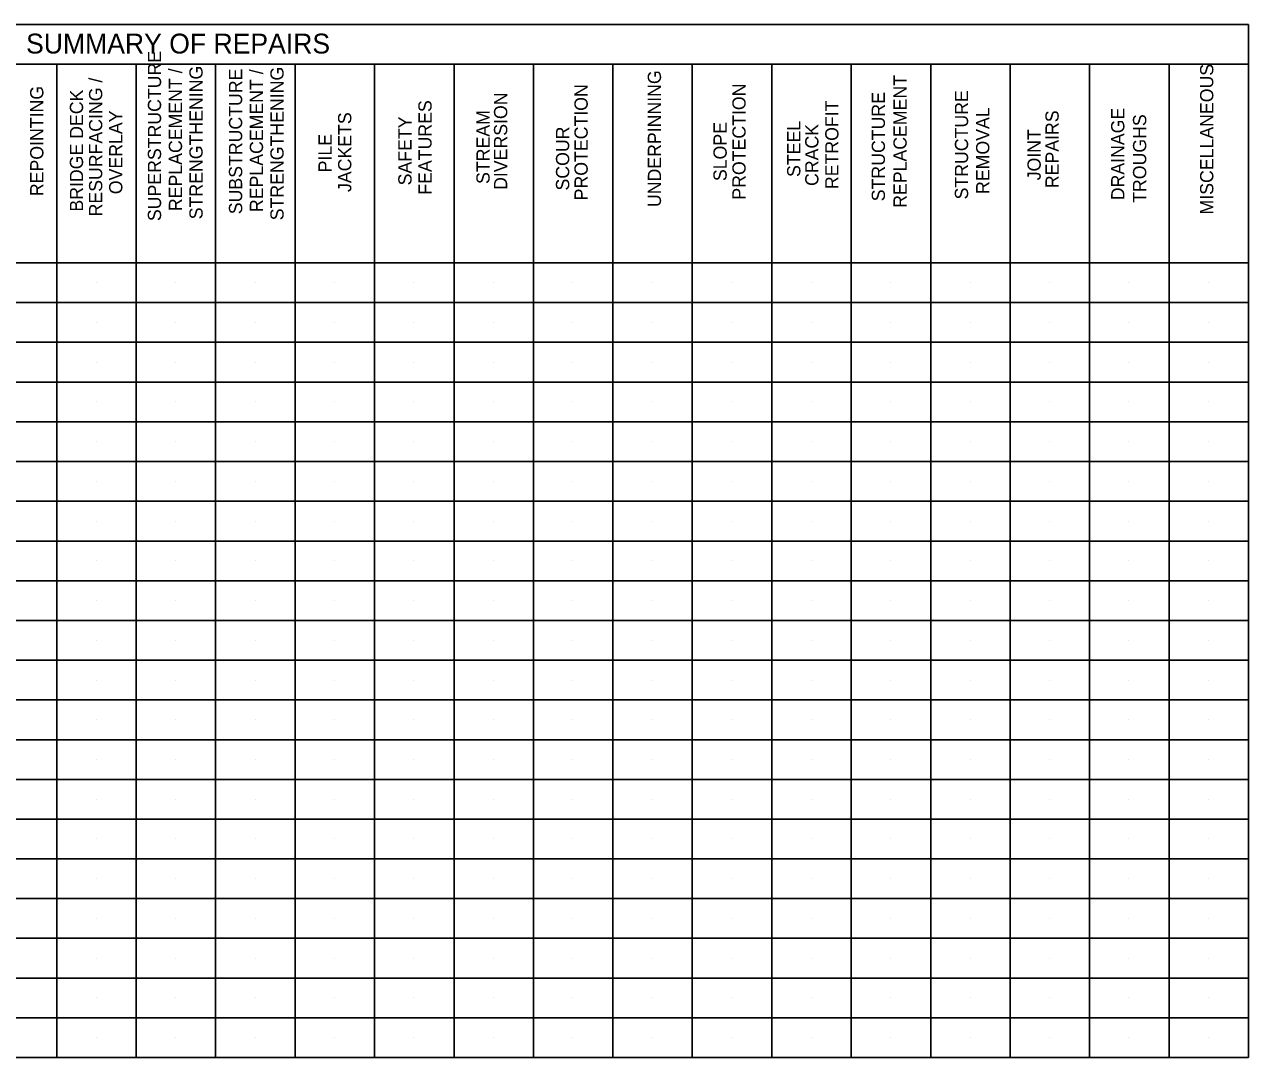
# Model space of a CAD drawing. Extents: x 3.4 to 29.9, y 7.8 to 20.1.
# Drawn here: x 15.32 to 29.88, y 7.79 to 20.08 of the extents above; entities that cross this region are included whole.
import ezdxf

# ---------------------------------------------------------------- set-up
doc = ezdxf.new("R2010")
doc.units = 0
doc.layers.add('ANNO-NOTE', color=7, linetype='Continuous')

msp = doc.modelspace()

# ---------------------------------------------------------------- linework, layer by layer
at = {"layer": 'ANNO-NOTE'}
for p, q in [((3.421, 20.077), (29.877, 20.077)), ((29.877, 20.077), (29.877, 7.794)), ((3.421, 19.605), (29.877, 19.605)), ((15.704, 17.242), (15.704, 19.605)), ((16.649, 17.242), (16.649, 19.605)), ((17.594, 17.242), (17.594, 19.605)), ((18.539, 17.242), (18.539, 19.605)), ((19.484, 17.242), (19.484, 19.605)), ((20.429, 17.242), (20.429, 19.605)), ((21.373, 17.242), (21.373, 19.605)), ((22.318, 17.242), (22.318, 19.605)), ((23.263, 17.242), (23.263, 19.605)), ((24.208, 17.242), (24.208, 19.605)), ((25.153, 17.242), (25.153, 19.605)), ((26.098, 17.242), (26.098, 19.605)), ((27.043, 17.242), (27.043, 19.605)), ((27.988, 17.242), (27.988, 19.605)), ((28.933, 17.242), (28.933, 19.605)), ((3.421, 17.242), (29.877, 17.242)), ((15.704, 17.242), (15.704, 7.794)), ((16.649, 17.242), (16.649, 7.794)), ((17.594, 17.242), (17.594, 7.794)), ((18.539, 17.242), (18.539, 7.794)), ((19.484, 17.242), (19.484, 7.794)), ((20.429, 17.242), (20.429, 7.794)), ((21.373, 17.242), (21.373, 7.794)), ((22.318, 17.242), (22.318, 7.794)), ((23.263, 17.242), (23.263, 7.794)), ((24.208, 17.242), (24.208, 7.794)), ((25.153, 17.242), (25.153, 7.794)), ((26.098, 17.242), (26.098, 7.794)), ((27.043, 17.242), (27.043, 7.794)), ((27.988, 17.242), (27.988, 7.794)), ((28.933, 17.242), (28.933, 7.794)), ((16.173, 17.006), (16.173, 17.006)), ((16.173, 17.006), (16.173, 17.006)), ((17.118, 17.006), (17.118, 17.006)), ((17.118, 17.006), (17.118, 17.006)), ((18.063, 17.006), (18.063, 17.006)), ((18.063, 17.006), (18.063, 17.006)), ((19.007, 17.006), (19.007, 17.006)), ((19.007, 17.006), (19.007, 17.006)), ((19.952, 17.006), (19.952, 17.006)), ((19.952, 17.006), (19.952, 17.006)), ((20.897, 17.006), (20.897, 17.006)), ((20.897, 17.006), (20.897, 17.006)), ((21.842, 17.006), (21.842, 17.006)), ((21.842, 17.006), (21.842, 17.006)), ((22.787, 17.006), (22.787, 17.006)), ((22.787, 17.006), (22.787, 17.006)), ((23.732, 17.006), (23.732, 17.006)), ((23.732, 17.006), (23.732, 17.006)), ((24.677, 17.006), (24.677, 17.006)), ((24.677, 17.006), (24.677, 17.006)), ((25.622, 17.006), (25.622, 17.006)), ((25.622, 17.006), (25.622, 17.006)), ((26.567, 17.006), (26.567, 17.006)), ((26.567, 17.006), (26.567, 17.006)), ((27.511, 17.006), (27.511, 17.006)), ((27.511, 17.006), (27.511, 17.006)), ((28.456, 17.006), (28.456, 17.006)), ((28.456, 17.006), (28.456, 17.006)), ((29.401, 17.006), (29.401, 17.006)), ((29.401, 17.006), (29.401, 17.006)), ((3.421, 16.77), (29.877, 16.77)), ((16.173, 16.534), (16.173, 16.534)), ((16.173, 16.534), (16.173, 16.534)), ((16.173, 16.534), (16.173, 16.534)), ((17.118, 16.534), (17.118, 16.534)), ((17.118, 16.534), (17.118, 16.534)), ((17.118, 16.534), (17.118, 16.534)), ((18.063, 16.534), (18.063, 16.534)), ((18.063, 16.534), (18.063, 16.534)), ((18.063, 16.534), (18.063, 16.534)), ((19.007, 16.534), (19.007, 16.534)), ((19.007, 16.534), (19.007, 16.534)), ((19.007, 16.534), (19.007, 16.534)), ((19.952, 16.534), (19.952, 16.534)), ((19.952, 16.534), (19.952, 16.534)), ((19.952, 16.534), (19.952, 16.534)), ((20.897, 16.534), (20.897, 16.534)), ((20.897, 16.534), (20.897, 16.534)), ((20.897, 16.534), (20.897, 16.534)), ((21.842, 16.534), (21.842, 16.534)), ((21.842, 16.534), (21.842, 16.534)), ((21.842, 16.534), (21.842, 16.534)), ((22.787, 16.534), (22.787, 16.534)), ((22.787, 16.534), (22.787, 16.534)), ((22.787, 16.534), (22.787, 16.534)), ((23.732, 16.534), (23.732, 16.534)), ((23.732, 16.534), (23.732, 16.534)), ((23.732, 16.534), (23.732, 16.534)), ((24.677, 16.534), (24.677, 16.534)), ((24.677, 16.534), (24.677, 16.534)), ((24.677, 16.534), (24.677, 16.534)), ((25.622, 16.534), (25.622, 16.534)), ((25.622, 16.534), (25.622, 16.534)), ((25.622, 16.534), (25.622, 16.534)), ((26.567, 16.534), (26.567, 16.534)), ((26.567, 16.534), (26.567, 16.534)), ((26.567, 16.534), (26.567, 16.534)), ((27.511, 16.534), (27.511, 16.534)), ((27.511, 16.534), (27.511, 16.534)), ((27.511, 16.534), (27.511, 16.534)), ((28.456, 16.534), (28.456, 16.534)), ((28.456, 16.534), (28.456, 16.534)), ((28.456, 16.534), (28.456, 16.534)), ((29.401, 16.534), (29.401, 16.534)), ((29.401, 16.534), (29.401, 16.534)), ((29.401, 16.534), (29.401, 16.534)), ((3.421, 16.298), (29.877, 16.298)), ((16.173, 16.061), (16.173, 16.061)), ((17.118, 16.061), (17.118, 16.061)), ((18.063, 16.061), (18.063, 16.061)), ((19.007, 16.061), (19.007, 16.061)), ((19.952, 16.061), (19.952, 16.061)), ((20.897, 16.061), (20.897, 16.061)), ((21.842, 16.061), (21.842, 16.061)), ((22.787, 16.061), (22.787, 16.061)), ((23.732, 16.061), (23.732, 16.061)), ((24.677, 16.061), (24.677, 16.061)), ((25.622, 16.061), (25.622, 16.061)), ((26.567, 16.061), (26.567, 16.061)), ((27.511, 16.061), (27.511, 16.061)), ((28.456, 16.061), (28.456, 16.061)), ((29.401, 16.061), (29.401, 16.061)), ((3.421, 15.825), (29.877, 15.825)), ((16.173, 15.589), (16.173, 15.589)), ((17.118, 15.589), (17.118, 15.589)), ((18.063, 15.589), (18.063, 15.589)), ((19.007, 15.589), (19.007, 15.589)), ((19.952, 15.589), (19.952, 15.589)), ((20.897, 15.589), (20.897, 15.589)), ((21.842, 15.589), (21.842, 15.589)), ((22.787, 15.589), (22.787, 15.589)), ((23.732, 15.589), (23.732, 15.589)), ((24.677, 15.589), (24.677, 15.589)), ((25.622, 15.589), (25.622, 15.589)), ((26.567, 15.589), (26.567, 15.589)), ((27.511, 15.589), (27.511, 15.589)), ((28.456, 15.589), (28.456, 15.589)), ((29.401, 15.589), (29.401, 15.589)), ((3.421, 15.353), (29.877, 15.353)), ((16.173, 15.116), (16.173, 15.116)), ((17.118, 15.116), (17.118, 15.116)), ((18.063, 15.116), (18.063, 15.116)), ((19.007, 15.116), (19.007, 15.116)), ((19.952, 15.116), (19.952, 15.116)), ((20.897, 15.116), (20.897, 15.116)), ((21.842, 15.116), (21.842, 15.116)), ((22.787, 15.116), (22.787, 15.116)), ((23.732, 15.116), (23.732, 15.116)), ((24.677, 15.116), (24.677, 15.116)), ((25.622, 15.116), (25.622, 15.116)), ((26.567, 15.116), (26.567, 15.116)), ((27.511, 15.116), (27.511, 15.116)), ((28.456, 15.116), (28.456, 15.116)), ((29.401, 15.116), (29.401, 15.116)), ((3.421, 14.88), (29.877, 14.88)), ((16.173, 14.644), (16.173, 14.644)), ((17.118, 14.644), (17.118, 14.644)), ((18.063, 14.644), (18.063, 14.644)), ((19.007, 14.644), (19.007, 14.644)), ((19.952, 14.644), (19.952, 14.644)), ((20.897, 14.644), (20.897, 14.644)), ((21.842, 14.644), (21.842, 14.644)), ((22.787, 14.644), (22.787, 14.644)), ((23.732, 14.644), (23.732, 14.644)), ((24.677, 14.644), (24.677, 14.644)), ((25.622, 14.644), (25.622, 14.644)), ((26.567, 14.644), (26.567, 14.644)), ((27.511, 14.644), (27.511, 14.644)), ((28.456, 14.644), (28.456, 14.644)), ((29.401, 14.644), (29.401, 14.644)), ((3.421, 14.408), (29.877, 14.408)), ((16.173, 14.172), (16.173, 14.172)), ((17.118, 14.172), (17.118, 14.172)), ((18.063, 14.172), (18.063, 14.172)), ((19.007, 14.172), (19.007, 14.172)), ((19.952, 14.172), (19.952, 14.172)), ((20.897, 14.172), (20.897, 14.172)), ((21.842, 14.172), (21.842, 14.172)), ((22.787, 14.172), (22.787, 14.172)), ((23.732, 14.172), (23.732, 14.172)), ((24.677, 14.172), (24.677, 14.172)), ((25.622, 14.172), (25.622, 14.172)), ((26.567, 14.172), (26.567, 14.172)), ((27.511, 14.172), (27.511, 14.172)), ((28.456, 14.172), (28.456, 14.172)), ((29.401, 14.172), (29.401, 14.172)), ((3.421, 13.935), (29.877, 13.935)), ((16.173, 13.699), (16.173, 13.699)), ((17.118, 13.699), (17.118, 13.699)), ((18.063, 13.699), (18.063, 13.699)), ((19.007, 13.699), (19.007, 13.699)), ((19.952, 13.699), (19.952, 13.699)), ((20.897, 13.699), (20.897, 13.699)), ((21.842, 13.699), (21.842, 13.699)), ((22.787, 13.699), (22.787, 13.699)), ((23.732, 13.699), (23.732, 13.699)), ((24.677, 13.699), (24.677, 13.699)), ((25.622, 13.699), (25.622, 13.699)), ((26.567, 13.699), (26.567, 13.699)), ((27.511, 13.699), (27.511, 13.699)), ((28.456, 13.699), (28.456, 13.699)), ((29.401, 13.699), (29.401, 13.699)), ((3.421, 13.463), (29.877, 13.463)), ((16.173, 13.227), (16.173, 13.227)), ((17.118, 13.227), (17.118, 13.227)), ((18.063, 13.227), (18.063, 13.227)), ((19.007, 13.227), (19.007, 13.227)), ((19.952, 13.227), (19.952, 13.227)), ((20.897, 13.227), (20.897, 13.227)), ((21.842, 13.227), (21.842, 13.227)), ((22.787, 13.227), (22.787, 13.227)), ((23.732, 13.227), (23.732, 13.227)), ((24.677, 13.227), (24.677, 13.227)), ((25.622, 13.227), (25.622, 13.227)), ((26.567, 13.227), (26.567, 13.227)), ((27.511, 13.227), (27.511, 13.227)), ((28.456, 13.227), (28.456, 13.227)), ((29.401, 13.227), (29.401, 13.227)), ((3.421, 12.991), (29.877, 12.991)), ((16.173, 12.754), (16.173, 12.754)), ((17.118, 12.754), (17.118, 12.754)), ((18.063, 12.754), (18.063, 12.754)), ((19.007, 12.754), (19.007, 12.754)), ((19.952, 12.754), (19.952, 12.754)), ((20.897, 12.754), (20.897, 12.754)), ((21.842, 12.754), (21.842, 12.754)), ((22.787, 12.754), (22.787, 12.754)), ((23.732, 12.754), (23.732, 12.754)), ((24.677, 12.754), (24.677, 12.754)), ((25.622, 12.754), (25.622, 12.754)), ((26.567, 12.754), (26.567, 12.754)), ((27.511, 12.754), (27.511, 12.754)), ((28.456, 12.754), (28.456, 12.754)), ((29.401, 12.754), (29.401, 12.754)), ((3.421, 12.518), (29.877, 12.518)), ((16.173, 12.282), (16.173, 12.282)), ((17.118, 12.282), (17.118, 12.282)), ((18.063, 12.282), (18.063, 12.282)), ((19.007, 12.282), (19.007, 12.282)), ((19.952, 12.282), (19.952, 12.282)), ((20.897, 12.282), (20.897, 12.282)), ((21.842, 12.282), (21.842, 12.282)), ((22.787, 12.282), (22.787, 12.282)), ((23.732, 12.282), (23.732, 12.282)), ((24.677, 12.282), (24.677, 12.282)), ((25.622, 12.282), (25.622, 12.282)), ((26.567, 12.282), (26.567, 12.282)), ((27.511, 12.282), (27.511, 12.282)), ((28.456, 12.282), (28.456, 12.282)), ((29.401, 12.282), (29.401, 12.282)), ((3.421, 12.046), (29.877, 12.046)), ((16.173, 11.809), (16.173, 11.809)), ((17.118, 11.809), (17.118, 11.809)), ((18.063, 11.809), (18.063, 11.809)), ((19.007, 11.809), (19.007, 11.809)), ((19.952, 11.809), (19.952, 11.809)), ((20.897, 11.809), (20.897, 11.809)), ((21.842, 11.809), (21.842, 11.809)), ((22.787, 11.809), (22.787, 11.809)), ((23.732, 11.809), (23.732, 11.809)), ((24.677, 11.809), (24.677, 11.809)), ((25.622, 11.809), (25.622, 11.809)), ((26.567, 11.809), (26.567, 11.809)), ((27.511, 11.809), (27.511, 11.809)), ((28.456, 11.809), (28.456, 11.809)), ((29.401, 11.809), (29.401, 11.809)), ((3.421, 11.573), (29.877, 11.573)), ((16.173, 11.337), (16.173, 11.337)), ((17.118, 11.337), (17.118, 11.337)), ((18.063, 11.337), (18.063, 11.337)), ((19.007, 11.337), (19.007, 11.337)), ((19.952, 11.337), (19.952, 11.337)), ((20.897, 11.337), (20.897, 11.337)), ((21.842, 11.337), (21.842, 11.337)), ((22.787, 11.337), (22.787, 11.337)), ((23.732, 11.337), (23.732, 11.337)), ((24.677, 11.337), (24.677, 11.337)), ((25.622, 11.337), (25.622, 11.337)), ((26.567, 11.337), (26.567, 11.337)), ((27.511, 11.337), (27.511, 11.337)), ((28.456, 11.337), (28.456, 11.337)), ((29.401, 11.337), (29.401, 11.337)), ((3.421, 11.101), (29.877, 11.101)), ((16.173, 10.864), (16.173, 10.864)), ((16.173, 10.864), (16.173, 10.864)), ((17.118, 10.864), (17.118, 10.864)), ((17.118, 10.864), (17.118, 10.864)), ((18.063, 10.864), (18.063, 10.864)), ((18.063, 10.864), (18.063, 10.864)), ((19.007, 10.864), (19.007, 10.864)), ((19.007, 10.864), (19.007, 10.864)), ((19.952, 10.864), (19.952, 10.864)), ((19.952, 10.864), (19.952, 10.864)), ((20.897, 10.864), (20.897, 10.864)), ((20.897, 10.864), (20.897, 10.864)), ((21.842, 10.864), (21.842, 10.864)), ((21.842, 10.864), (21.842, 10.864)), ((22.787, 10.864), (22.787, 10.864)), ((22.787, 10.864), (22.787, 10.864)), ((23.732, 10.864), (23.732, 10.864)), ((23.732, 10.864), (23.732, 10.864)), ((24.677, 10.864), (24.677, 10.864)), ((24.677, 10.864), (24.677, 10.864)), ((25.622, 10.864), (25.622, 10.864)), ((25.622, 10.864), (25.622, 10.864)), ((26.567, 10.864), (26.567, 10.864)), ((26.567, 10.864), (26.567, 10.864)), ((27.511, 10.864), (27.511, 10.864)), ((27.511, 10.864), (27.511, 10.864)), ((28.456, 10.864), (28.456, 10.864)), ((28.456, 10.864), (28.456, 10.864)), ((29.401, 10.864), (29.401, 10.864)), ((29.401, 10.864), (29.401, 10.864)), ((3.421, 10.628), (29.877, 10.628)), ((16.173, 10.392), (16.173, 10.392)), ((17.118, 10.392), (17.118, 10.392)), ((18.063, 10.392), (18.063, 10.392)), ((19.007, 10.392), (19.007, 10.392)), ((19.952, 10.392), (19.952, 10.392)), ((20.897, 10.392), (20.897, 10.392)), ((21.842, 10.392), (21.842, 10.392)), ((22.787, 10.392), (22.787, 10.392)), ((23.732, 10.392), (23.732, 10.392)), ((24.677, 10.392), (24.677, 10.392)), ((25.622, 10.392), (25.622, 10.392)), ((26.567, 10.392), (26.567, 10.392)), ((27.511, 10.392), (27.511, 10.392)), ((28.456, 10.392), (28.456, 10.392)), ((29.401, 10.392), (29.401, 10.392)), ((3.421, 10.156), (29.877, 10.156)), ((16.173, 9.92), (16.173, 9.92)), ((17.118, 9.92), (17.118, 9.92)), ((18.063, 9.92), (18.063, 9.92)), ((19.007, 9.92), (19.007, 9.92)), ((19.952, 9.92), (19.952, 9.92)), ((20.897, 9.92), (20.897, 9.92)), ((21.842, 9.92), (21.842, 9.92)), ((22.787, 9.92), (22.787, 9.92)), ((23.732, 9.92), (23.732, 9.92)), ((24.677, 9.92), (24.677, 9.92)), ((25.622, 9.92), (25.622, 9.92)), ((26.567, 9.92), (26.567, 9.92)), ((27.511, 9.92), (27.511, 9.92)), ((28.456, 9.92), (28.456, 9.92)), ((29.401, 9.92), (29.401, 9.92)), ((3.421, 9.683), (29.877, 9.683)), ((16.173, 9.447), (16.173, 9.447)), ((17.118, 9.447), (17.118, 9.447)), ((18.063, 9.447), (18.063, 9.447)), ((19.007, 9.447), (19.007, 9.447)), ((19.952, 9.447), (19.952, 9.447)), ((20.897, 9.447), (20.897, 9.447)), ((21.842, 9.447), (21.842, 9.447)), ((22.787, 9.447), (22.787, 9.447)), ((23.732, 9.447), (23.732, 9.447)), ((24.677, 9.447), (24.677, 9.447)), ((25.622, 9.447), (25.622, 9.447)), ((26.567, 9.447), (26.567, 9.447)), ((27.511, 9.447), (27.511, 9.447)), ((28.456, 9.447), (28.456, 9.447)), ((29.401, 9.447), (29.401, 9.447)), ((3.421, 9.211), (29.877, 9.211)), ((16.173, 8.975), (16.173, 8.975)), ((17.118, 8.975), (17.118, 8.975)), ((18.063, 8.975), (18.063, 8.975)), ((19.007, 8.975), (19.007, 8.975)), ((19.952, 8.975), (19.952, 8.975)), ((20.897, 8.975), (20.897, 8.975)), ((21.842, 8.975), (21.842, 8.975)), ((22.787, 8.975), (22.787, 8.975)), ((23.732, 8.975), (23.732, 8.975)), ((24.677, 8.975), (24.677, 8.975)), ((25.622, 8.975), (25.622, 8.975)), ((26.567, 8.975), (26.567, 8.975)), ((27.511, 8.975), (27.511, 8.975)), ((28.456, 8.975), (28.456, 8.975)), ((29.401, 8.975), (29.401, 8.975)), ((3.421, 8.739), (29.877, 8.739)), ((16.173, 8.502), (16.173, 8.502)), ((17.118, 8.502), (17.118, 8.502)), ((18.063, 8.502), (18.063, 8.502)), ((19.007, 8.502), (19.007, 8.502)), ((19.952, 8.502), (19.952, 8.502)), ((20.897, 8.502), (20.897, 8.502)), ((21.842, 8.502), (21.842, 8.502)), ((22.787, 8.502), (22.787, 8.502)), ((23.732, 8.502), (23.732, 8.502)), ((24.677, 8.502), (24.677, 8.502)), ((25.622, 8.502), (25.622, 8.502)), ((26.567, 8.502), (26.567, 8.502)), ((27.511, 8.502), (27.511, 8.502)), ((28.456, 8.502), (28.456, 8.502)), ((29.401, 8.502), (29.401, 8.502)), ((3.421, 8.266), (29.877, 8.266)), ((16.173, 8.03), (16.173, 8.03)), ((17.118, 8.03), (17.118, 8.03)), ((18.063, 8.03), (18.063, 8.03)), ((19.007, 8.03), (19.007, 8.03)), ((19.952, 8.03), (19.952, 8.03)), ((20.897, 8.03), (20.897, 8.03)), ((21.842, 8.03), (21.842, 8.03)), ((22.787, 8.03), (22.787, 8.03)), ((23.732, 8.03), (23.732, 8.03)), ((24.677, 8.03), (24.677, 8.03)), ((25.622, 8.03), (25.622, 8.03)), ((26.567, 8.03), (26.567, 8.03)), ((27.511, 8.03), (27.511, 8.03)), ((28.456, 8.03), (28.456, 8.03)), ((29.401, 8.03), (29.401, 8.03)), ((3.421, 7.794), (29.877, 7.794))]:
    msp.add_line(p, q, dxfattribs=at)

# ---------------------------------------------------------------- texts
msp.add_text('SUMMARY OF REPAIRS', height=0.23622, dxfattribs=at).set_placement((15.34, 19.732))
for s, height, p in [('SUPERSTRUCTURE', 0.15748, (16.946, 17.739)), ('REPLACEMENT /', 0.15748, (17.195, 17.858)), ('STRENGTHENING ', 0.15748, (17.44, 17.761)), ('SUBSTRUCTURE', 0.15748, (17.91, 17.821)), ('REPLACEMENT /', 0.15748, (18.158, 17.847)), ('STRENGTHENING ', 0.15748, (18.403, 17.749)), ('UNDERPINNING', 0.15748, (22.891, 17.906)), ('MISCELLANEOUS', 0.15748, (29.459, 17.818)), ('RESURFACING /', 0.15748, (16.246, 17.795)), ('REPLACEMENT', 0.15748, (25.812, 17.897)), ('REPOINTING', 0.1575, (15.546, 18.036)), ('BRIDGE DECK', 0.15748, (16.018, 17.852)), ('DIVERSION', 0.1575, (21.062, 18.11)), ('PROTECTION', 0.1575, (22.019, 17.986)), ('PROTECTION', 0.1575, (23.897, 17.994)), ('STRUCTURE', 0.1575, (25.554, 17.975)), ('STRUCTURE', 0.1575, (26.543, 17.997)), ('FEATURES', 0.1575, (20.163, 18.053)), ('RETROFIT', 0.1575, (25.001, 18.12)), ('REMOVAL', 0.1575, (26.795, 18.062)), ('DRAINAGE', 0.1575, (28.401, 17.987)), ('OVERLAY', 0.1575, (16.485, 18.059)), ('JACKETS', 0.1575, (19.208, 18.085)), ('SAFETY', 0.1575, (19.924, 18.164)), ('STREAM', 0.1575, (20.853, 18.181)), ('STEEL ', 0.1575, (24.548, 18.264)), ('REPAIRS', 0.1575, (27.62, 18.131)), ('TROUGHS ', 0.1575, (28.661, 17.956)), ('SCOUR', 0.1575, (21.799, 18.103)), ('SLOPE', 0.1575, (23.672, 18.215)), ('CRACK', 0.1575, (24.763, 18.157)), ('JOINT', 0.1575, (27.406, 18.224)), ('PILE', 0.1575, (18.974, 18.319))]:
    msp.add_text(s, height=height, rotation=90, dxfattribs=at).set_placement(p)

doc.saveas('drawing.dxf')
